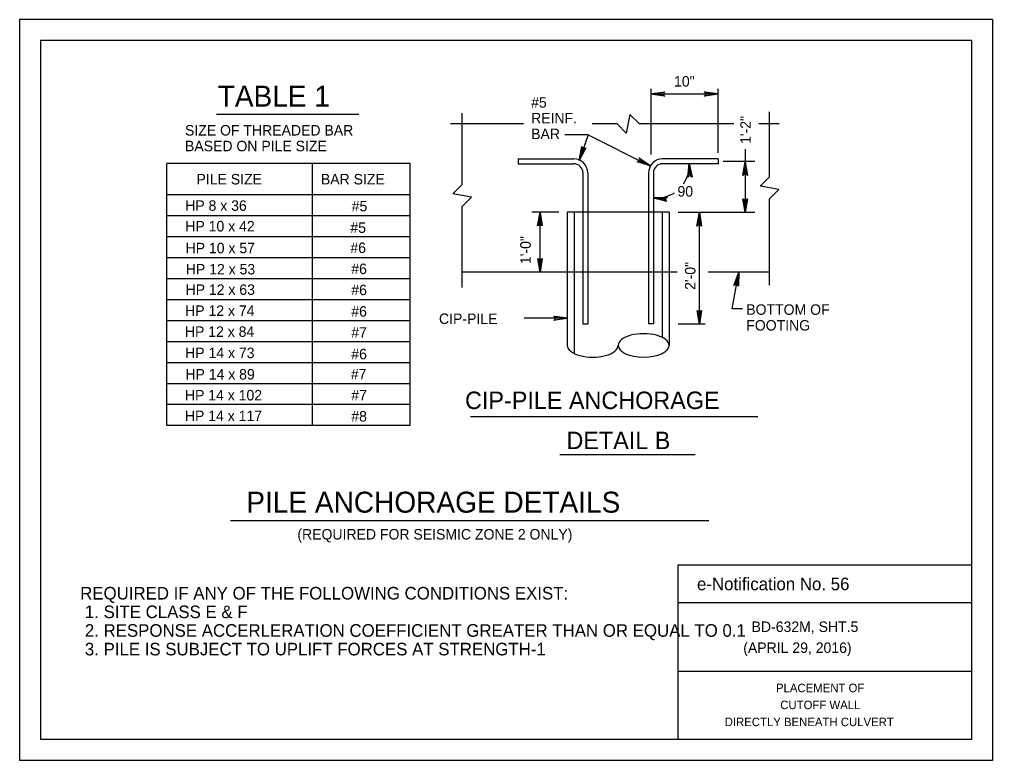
# Model space of a CAD drawing. Extents: x 235 to 2276, y 116 to 1308.
# Drawn here: x 234.9 to 513.3, y 787.6 to 999.6 of the extents above; entities that cross this region are included whole.
import ezdxf

# ---------------------------------------------------------------- set-up
doc = ezdxf.new("R2010")
doc.units = 0
doc.layers.add('1', color=7, linetype='Continuous')
doc.layers.add('2', color=7, linetype='Continuous')

msp = doc.modelspace()

# ---------------------------------------------------------------- linework, layer by layer
at = {"layer": '1'}
for p, q in [((415.63, 960.95), (415.63, 979.79)), ((415.63, 978.3), (434.84, 978.3)), ((434.84, 961.44), (434.84, 979.79)), ((332, 972.44), (291.32, 972.44)), ((361.49, 972.77), (361.49, 952.33)), ((409.54, 972.45), (408.54, 967.11)), ((412.3, 969.69), (409.54, 972.45)), ((449.47, 973.2), (449.47, 954.5)), ((379.11, 969.69), (358.27, 969.69)), ((405.96, 969.69), (398.82, 969.69)), ((408.54, 967.11), (405.96, 969.69)), ((439.36, 969.69), (412.3, 969.69)), ((452.25, 969.69), (446.46, 969.69)), ((397.65, 966.6), (390.93, 966.6)), ((397.65, 966.6), (395.37, 960.03)), ((397.65, 966.6), (415.07, 957.81)), ((442.63, 944.43), (442.63, 962.53)), ((346.72, 958.4), (277.08, 958.4)), ((277.08, 883.4), (277.08, 958.4)), ((318.81, 883.4), (318.81, 958.4)), ((346.72, 883.4), (346.72, 958.4)), ((377.62, 959.72), (393.53, 959.72)), ((377.62, 959.72), (377.62, 958.32)), ((377.62, 958.32), (393.53, 958.32)), ((434.84, 959.72), (418.93, 959.72)), ((434.84, 958.32), (418.93, 958.32)), ((434.84, 959.72), (434.84, 958.32)), ((445.32, 958.96), (436.26, 958.96)), ((396.13, 955.72), (396.13, 944.43)), ((397.53, 955.72), (397.53, 944.43)), ((414.93, 955.72), (414.93, 944.43)), ((416.33, 955.72), (416.33, 944.43)), ((358.91, 949.75), (361.49, 952.33)), ((446.89, 951.92), (449.47, 954.5)), ((346.72, 949.4), (277.08, 949.4)), ((364.25, 948.74), (358.91, 949.75)), ((452.23, 950.92), (446.89, 951.92)), ((449.47, 948.16), (452.23, 950.92)), ((361.49, 945.98), (364.25, 948.74)), ((449.47, 948.16), (449.47, 923.54)), ((361.49, 945.98), (361.49, 922.9)), ((389.28, 944.43), (381.57, 944.43)), ((383.89, 927.31), (383.89, 944.43)), ((420.79, 944.43), (391.67, 944.43)), ((391.67, 944.43), (391.67, 927.31)), ((393.64, 944.43), (393.64, 904.06)), ((396.13, 944.43), (396.13, 912.48)), ((397.53, 944.43), (397.53, 912.48)), ((414.93, 944.43), (414.93, 912.48)), ((416.33, 944.43), (416.33, 912.48)), ((418.82, 944.43), (418.82, 908.64)), ((420.79, 944.43), (420.79, 927.31)), ((423.37, 944.43), (445.32, 944.43)), ((429.46, 912.48), (429.46, 944.43)), ((346.72, 943.4), (277.08, 943.4)), ((346.72, 937.4), (277.08, 937.4)), ((346.72, 931.4), (277.08, 931.4)), ((423.08, 927.31), (361.49, 927.31)), ((391.67, 927.31), (391.67, 906.35)), ((420.79, 927.31), (420.79, 906.35)), ((449.47, 927.31), (431.98, 927.31)), ((438.87, 916.81), (440.74, 927.31)), ((346.72, 925.4), (277.08, 925.4)), ((346.72, 919.4), (277.08, 919.4)), ((441.77, 916.81), (438.87, 916.81)), ((346.72, 913.4), (277.08, 913.4)), ((391.67, 914.14), (379.36, 914.14)), ((396.13, 912.48), (397.53, 912.48)), ((416.33, 912.48), (414.93, 912.48)), ((423.37, 912.48), (431.08, 912.48)), ((346.72, 907.4), (277.08, 907.4)), ((346.72, 901.4), (277.08, 901.4)), ((346.72, 895.4), (277.08, 895.4)), ((346.72, 889.4), (277.08, 889.4)), ((363.94, 886.05), (446.21, 886.05)), ((346.72, 883.4), (277.08, 883.4)), ((428.25, 875.03), (389.58, 875.03)), ((295.36, 856.23), (432.17, 856.23))]:
    msp.add_line(p, q, dxfattribs=at)
for points in [[(419.35, 977.79), (419.22, 978.04), (415.6, 978.29), (419.35, 977.79), (419.6, 977.67), (415.6, 978.29), (419.22, 978.42), (419.35, 978.67), (415.6, 978.29), (419.6, 978.92), (419.35, 978.67)], [(431.05, 978.79), (431.17, 978.54), (434.8, 978.29), (431.05, 978.79), (430.8, 978.91), (434.8, 978.29), (431.17, 978.16), (431.05, 977.79), (434.8, 978.29), (430.8, 977.66), (431.05, 977.79)], [(396.79, 962.7), (396.48, 962.66), (395.1, 959.29), (396.79, 962.7), (397.01, 962.83), (395.1, 959.29), (396.12, 962.78), (395.91, 963), (395.1, 959.29), (395.8, 963.25), (395.91, 963)], [(412.35, 959.81), (412.36, 959.5), (415.51, 957.68), (412.35, 959.81), (412.25, 960.04), (415.51, 957.68), (412.19, 959.16), (411.95, 958.98), (415.51, 957.68), (411.68, 958.91), (411.95, 958.98)], [(426.27, 954.63), (426.54, 954.78), (426.54, 958.43), (426.27, 954.63), (426.12, 954.43), (426.54, 958.43), (426.92, 954.81), (427.19, 954.69), (426.54, 958.43), (427.39, 954.5), (427.19, 954.69)], [(442.11, 955.24), (442.36, 955.36), (442.61, 958.99), (442.11, 955.24), (441.86, 954.99), (442.61, 958.99), (442.74, 955.36), (442.99, 955.24), (442.61, 958.99), (443.24, 954.99), (442.99, 955.24)], [(420, 947.71), (419.89, 948), (416.29, 948.57), (420, 947.71), (420.18, 947.52), (416.29, 948.57), (419.93, 948.37), (420.08, 948.63), (416.29, 948.57), (420.31, 948.79), (420.08, 948.63)], [(442.94, 948.18), (442.69, 948.06), (442.57, 944.43), (442.94, 948.18), (443.19, 948.31), (442.57, 944.43), (442.32, 948.06), (442.07, 948.18), (442.57, 944.43), (441.94, 948.31), (442.07, 948.18)], [(383.39, 940.76), (383.64, 940.89), (383.89, 944.51), (383.39, 940.76), (383.14, 940.51), (383.89, 944.51), (384.02, 940.89), (384.27, 940.76), (383.89, 944.51), (384.52, 940.51), (384.27, 940.76)], [(428.97, 940.72), (429.22, 940.84), (429.47, 944.47), (428.97, 940.72), (428.72, 940.47), (429.47, 944.47), (429.6, 940.84), (429.85, 940.72), (429.47, 944.47), (430.1, 940.47), (429.85, 940.72)], [(384.28, 931.05), (384.03, 930.93), (383.91, 927.3), (384.28, 931.05), (384.53, 931.18), (383.91, 927.3), (383.66, 930.93), (383.41, 931.05), (383.91, 927.3), (383.28, 931.18), (383.41, 931.05)], [(439.63, 923.69), (439.9, 923.77), (440.74, 927.31), (439.63, 923.69), (439.34, 923.48), (440.74, 927.31), (440.27, 923.71), (440.49, 923.55), (440.74, 927.31), (440.7, 923.26), (440.49, 923.55)], [(429.85, 916.22), (429.6, 916.09), (429.48, 912.47), (429.85, 916.22), (430.1, 916.34), (429.48, 912.47), (429.23, 916.09), (428.98, 916.22), (429.48, 912.47), (428.85, 916.34), (428.98, 916.22)], [(388.05, 914.62), (388.18, 914.37), (391.8, 914.12), (388.05, 914.62), (387.8, 914.75), (391.8, 914.12), (388.18, 914), (388.05, 913.62), (391.8, 914.12), (387.8, 913.5), (388.05, 913.62)]]:
    msp.add_lwpolyline(points, dxfattribs=at)
for centre, radius, start, end in [((393.53, 955.72), 4, 0, 90), ((393.53, 955.72), 2.6, 0, 90), ((418.93, 955.72), 4, 90, 180), ((418.93, 955.72), 2.6, 90, 180), ((417.29, 957.81), 9.27, 325.6533, 3.1394), ((417.29, 957.81), 9.27, 264.1002, 302.8279)]:
    msp.add_arc(centre, radius, start, end, dxfattribs=at)
for centre, major_axis, start_param, end_param in [((413.51, 906.35), (7.28, 0), 0, 3.141598), ((398.95, 906.35), (-7.28, 0), 0, 3.141593), ((413.51, 906.35), (7.28, 0), 3.143175, 6.283185)]:
    msp.add_ellipse(centre, major_axis=major_axis, ratio=0.460563, start_param=start_param, end_param=end_param, dxfattribs=at)
at = {"layer": '2'}
for p, q in [((234.94, 999.59), (234.94, 787.59)), ((513.34, 999.59), (234.94, 999.59)), ((513.34, 999.59), (513.34, 787.59)), ((240.94, 993.59), (240.94, 793.59)), ((507.34, 993.59), (240.94, 993.59)), ((507.34, 993.59), (507.34, 793.59)), ((507.34, 843.49), (423.29, 843.49)), ((423.29, 843.49), (423.29, 793.59)), ((507.34, 832.66), (423.29, 832.66)), ((507.34, 813.09), (423.29, 813.09)), ((507.34, 793.59), (240.94, 793.59)), ((513.34, 787.59), (234.94, 787.59))]:
    msp.add_line(p, q, dxfattribs=at)

# ---------------------------------------------------------------- texts
at = {"layer": '1'}
for s, height, p in [('10"', 3.003, (422.22, 980.39)), ('TABLE 1', 6, (291.66, 974.65)), ('#5', 3, (381.33, 974.36)), ('REINF.', 3, (381.33, 969.86)), ('SIZE OF THREADED BAR', 3, (282.3, 966.39)), ('BAR', 3, (381.33, 965.36)), ('BASED ON PILE SIZE', 3, (282.3, 961.89)), ('PILE SIZE', 3, (285.59, 952.4)), ('BAR SIZE', 3, (321.18, 952.4)), ('90', 3, (423.2, 948.92)), ('HP 8 x 36', 3, (282.36, 944.85)), ('#5', 3, (330, 944.7)), ('HP 10 x 42', 3, (282.39, 938.95)), ('#5', 3, (329.62, 938.54)), ('HP 10 x 57', 3, (282.46, 932.7)), ('#6', 3, (329.62, 932.78)), ('HP 12 x 53', 3, (282.53, 926.65)), ('#6', 3, (329.88, 926.75)), ('HP 12 x 63', 3, (282.46, 920.81)), ('#6', 3, (329.88, 920.73)), ('HP 12 x 74', 3, (282.34, 914.78)), ('#6', 3, (329.88, 914.57)), ('BOTTOM OF', 3, (442.88, 915.1)), ('CIP-PILE', 3, (354.97, 912.47)), ('FOOTING', 3, (442.88, 910.6)), ('HP 12 x 84', 3, (282.27, 908.8)), ('#7', 3, (329.88, 908.55)), ('HP 14 x 73', 3, (282.34, 902.71)), ('#6', 3, (329.88, 902.39)), ('HP 14 x 89', 3, (282.41, 896.59)), ('#7', 3, (329.75, 896.63)), ('HP 14 x 102', 3, (282.27, 890.61)), ('#7', 3, (329.88, 890.6)), (' CIP-PILE ANCHORAGE', 5, (360.56, 888.14)), ('HP 14 x 117', 3, (282.27, 884.7)), ('#8', 3, (329.88, 884.58)), ('DETAIL B', 5, (391.43, 876.67)), ('PILE ANCHORAGE DETAILS', 6, (299.84, 858.5)), ('(REQUIRED FOR SEISMIC ZONE 2 ONLY)', 3, (314.45, 850.82)), ('REQUIRED IF ANY OF THE FOLLOWING CONDITIONS EXIST:', 3.6, (252.31, 833.66)), (' 1. SITE CLASS E & F', 3.6, (252.31, 828.33)), (' 2. RESPONSE ACCERLERATION COEFFICIENT GREATER THAN OR EQUAL TO 0.1', 3.6, (252.31, 823)), (' 3. PILE IS SUBJECT TO UPLIFT FORCES AT STRENGTH-1', 3.6, (252.31, 817.67))]:
    msp.add_text(s, height=height, dxfattribs=at).set_placement(p)
for s, p in [('1\'-2"', (444.17, 964)), ('1\'-0"', (381.22, 929.62)), ('2\'-0"', (428.34, 922.24))]:
    msp.add_text(s, height=3, rotation=90, dxfattribs=at).set_placement(p)
at = {"layer": '2'}
for s, height, p in [('e-Notification No. 56', 3.6, (428.78, 836.31)), ('BD-632M, SHT.5', 3, (444.4, 824.37)), ('(APRIL 29, 2016)', 3, (442.02, 818.37)), ('PLACEMENT OF', 2.43, (451.38, 807.15)), ('CUTOFF WALL', 2.43, (452.61, 802.29)), ('DIRECTLY BENEATH CULVERT', 2.43, (436.7, 797.43))]:
    msp.add_text(s, height=height, rotation=360, dxfattribs=at).set_placement(p)

doc.saveas('drawing.dxf')
